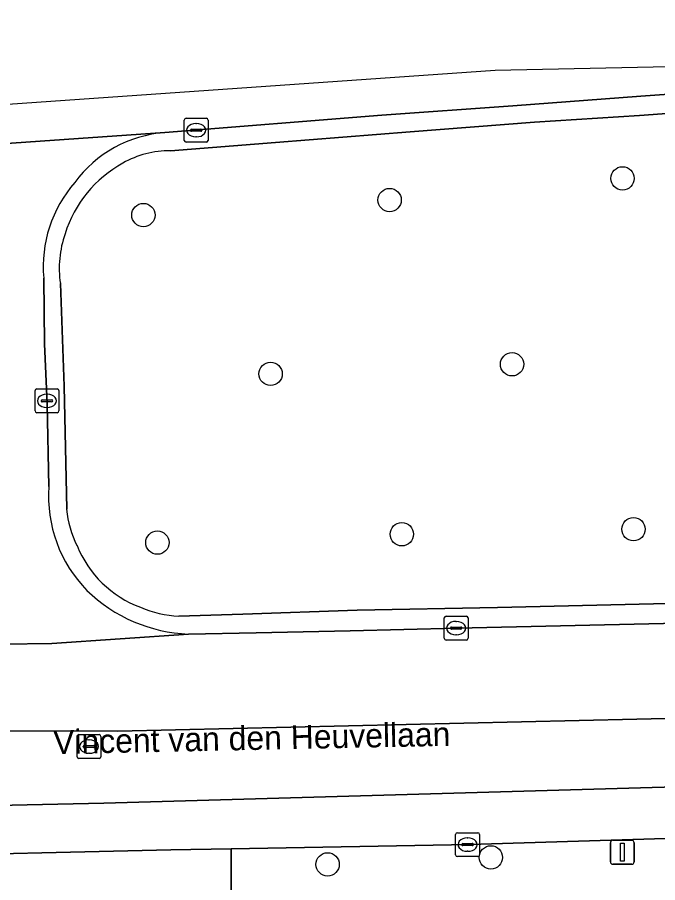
# Model space of a CAD drawing. Extents: x 160806 to 161707, y 383696 to 384148.
# Drawn here: x 161330.97 to 161357.82, y 384111.54 to 384147.79 of the extents above; entities that cross this region are included whole.
import ezdxf

# ---------------------------------------------------------------- set-up
doc = ezdxf.new("R2010")
doc.units = 0
for name, color, linetype in [('IMGEO_Berm_groen', 7, 'Continuous'), ('IMGEO_Boom', 7, 'Continuous'), ('IMGEO_Kolk', 7, 'Continuous'), ('IMGEO_Lichtmast', 7, 'Continuous'), ('IMGEO_Openbare_ruimte_label', 7, 'Continuous'), ('IMGEO_Rijbaan_lokaal_gesloten', 7, 'Continuous'), ('IMGEO_Rioolput', 7, 'Continuous'), ('IMGEO_Verkeerseiland_open', 7, 'Continuous'), ('IMGEO_Voetpad_open', 7, 'Continuous')]:
    doc.layers.add(name, color=color, linetype=linetype)

msp = doc.modelspace()

# ---------------------------------------------------------------- linework, layer by layer
at = {"layer": 'IMGEO_Berm_groen'}
for points in [[(161368.322, 384133.815), (161368.24, 384136.337), (161368.083, 384140.59), (161367.93, 384144.377), (161364.506, 384144.165), (161360.482, 384143.926), (161357.058, 384143.679), (161352.653, 384143.406), (161347.447, 384142.996), (161341.799, 384142.542), (161337.394, 384142.199)], [(161332.779, 384136.639), (161332.944, 384132.346), (161333.044, 384127.181)], [(161337.75, 384122.702), (161340.431, 384122.791), (161345.225, 384122.958), (161351.108, 384123.068), (161357.641, 384123.218), (161365.144, 384123.353), (161368.747, 384123.478), (161368.664, 384126.609), (161368.52, 384129.702), (161368.389, 384132.294), (161368.322, 384133.815)]]:
    msp.add_lwpolyline(points, dxfattribs=at)
for centre, radius, start, end in [((161337.351, 384138.259), 3.941, 89.3808, 119.716), ((161337.869, 384137.19), 5.126, 118.8204, 162.6198), ((161337.115, 384137.277), 4.383, 160.7646, 188.3704), ((161337.378, 384127.594), 4.354, 185.4426, 206.3586), ((161337.741, 384127.387), 4.6, 202.0341, 249.6037), ((161337.958, 384127.271), 4.574, 246.551, 267.3923)]:
    msp.add_arc(centre, radius, start, end, dxfattribs=at)
at = {"layer": 'IMGEO_Boom'}
for centre in [(161356.343, 384141.046), (161346.581, 384140.138), (161336.259, 384139.508), (161351.712, 384133.255), (161341.593, 384132.854), (161347.092, 384126.136), (161356.804, 384126.346), (161336.846, 384125.786), (161343.983, 384112.305), (161350.826, 384112.597)]:
    msp.add_circle(centre, 0.489, dxfattribs=at)
at = {"layer": 'IMGEO_Kolk'}
for p, q in [((161338.046, 384143.563), (161338.898, 384143.563)), ((161337.971, 384142.637), (161337.971, 384143.489)), ((161338.459, 384143.343), (161338.484, 384143.343)), ((161338.972, 384143.489), (161338.972, 384142.637)), ((161338.23, 384143.057), (161338.23, 384143.069)), ((161338.668, 384143.02), (161338.27, 384143.02)), ((161338.273, 384143.106), (161338.671, 384143.106)), ((161338.714, 384143.069), (161338.714, 384143.057)), ((161338.898, 384142.563), (161338.046, 384142.563)), ((161338.482, 384142.783), (161338.457, 384142.783)), ((161331.717, 384131.299), (161331.717, 384132.151)), ((161331.792, 384132.225), (161332.644, 384132.225)), ((161332.205, 384132.005), (161332.23, 384132.005)), ((161332.718, 384132.151), (161332.718, 384131.299)), ((161331.976, 384131.719), (161331.976, 384131.731)), ((161332.414, 384131.682), (161332.016, 384131.682)), ((161332.019, 384131.768), (161332.417, 384131.768)), ((161332.46, 384131.731), (161332.46, 384131.719)), ((161332.228, 384131.445), (161332.203, 384131.445)), ((161332.644, 384131.225), (161331.792, 384131.225)), ((161348.871, 384121.777), (161348.871, 384122.629)), ((161348.946, 384122.703), (161349.798, 384122.703)), ((161349.872, 384122.629), (161349.872, 384121.777)), ((161349.13, 384122.197), (161349.13, 384122.209)), ((161349.173, 384122.246), (161349.571, 384122.246)), ((161349.359, 384122.483), (161349.384, 384122.483)), ((161349.614, 384122.209), (161349.614, 384122.197)), ((161349.568, 384122.16), (161349.17, 384122.16)), ((161349.382, 384121.923), (161349.357, 384121.923)), ((161349.798, 384121.703), (161348.946, 384121.703)), ((161349.348, 384112.706), (161349.348, 384113.558)), ((161349.423, 384113.632), (161350.275, 384113.632)), ((161350.349, 384113.558), (161350.349, 384112.706)), ((161349.607, 384113.126), (161349.607, 384113.138)), ((161349.65, 384113.175), (161350.048, 384113.175)), ((161349.836, 384113.412), (161349.861, 384113.412)), ((161350.091, 384113.138), (161350.091, 384113.126)), ((161350.045, 384113.089), (161349.647, 384113.089)), ((161349.859, 384112.852), (161349.834, 384112.852)), ((161350.275, 384112.632), (161349.423, 384112.632))]:
    msp.add_line(p, q, dxfattribs=at)
for points in [[(161338.046, 384143.563), (161338.898, 384143.563)], [(161337.971, 384142.637), (161337.971, 384143.489)], [(161338.972, 384143.489), (161338.972, 384142.637)], [(161338.898, 384142.563), (161338.046, 384142.563)], [(161331.717, 384131.299), (161331.717, 384132.151)], [(161331.792, 384132.225), (161332.644, 384132.225)], [(161332.718, 384132.151), (161332.718, 384131.299)], [(161332.644, 384131.225), (161331.792, 384131.225)], [(161348.871, 384121.777), (161348.871, 384122.629)], [(161348.946, 384122.703), (161349.798, 384122.703)], [(161349.872, 384122.629), (161349.872, 384121.777)], [(161349.798, 384121.703), (161348.946, 384121.703)], [(161349.348, 384112.706), (161349.348, 384113.558)], [(161349.423, 384113.632), (161350.275, 384113.632)], [(161350.349, 384113.558), (161350.349, 384112.706)], [(161350.275, 384112.632), (161349.423, 384112.632)]]:
    msp.add_lwpolyline(points, dxfattribs=at)
for centre, radius, start, end in [((161338.048, 384143.487), 0.0765, 91.552, 178.448), ((161338.048, 384143.487), 0.0765, 91.552, 178.448), ((161338.896, 384143.487), 0.0765, 1.552, 88.448), ((161338.896, 384143.487), 0.0765, 1.552, 88.448), ((161338.27, 384143.066), 0.0403, 85.8775, 175.7526), ((161338.267, 384143.056), 0.0366, 178.938, 274.7102), ((161338.671, 384143.063), 0.043, 264.8664, 352.4533), ((161338.675, 384143.068), 0.0386, 1.7309, 96.639), ((161338.048, 384142.639), 0.0765, 181.552, 268.448), ((161338.048, 384142.639), 0.0765, 181.552, 268.448), ((161338.896, 384142.639), 0.0765, 271.552, 358.448), ((161338.896, 384142.639), 0.0765, 271.552, 358.448), ((161331.794, 384132.149), 0.0765, 91.552, 178.448), ((161331.794, 384132.149), 0.0765, 91.552, 178.448), ((161332.642, 384132.149), 0.0765, 1.552, 88.448), ((161332.642, 384132.149), 0.0765, 1.552, 88.448), ((161332.016, 384131.728), 0.0403, 85.8775, 175.7526), ((161332.013, 384131.718), 0.0366, 178.938, 274.7102), ((161332.417, 384131.725), 0.043, 264.8664, 352.4533), ((161332.421, 384131.73), 0.0386, 1.7309, 96.639), ((161331.794, 384131.301), 0.0765, 181.552, 268.448), ((161331.794, 384131.301), 0.0765, 181.552, 268.448), ((161332.642, 384131.301), 0.0765, 271.552, 358.448), ((161332.642, 384131.301), 0.0765, 271.552, 358.448), ((161348.948, 384122.627), 0.0765, 91.552, 178.448), ((161348.948, 384122.627), 0.0765, 91.552, 178.448), ((161349.796, 384122.627), 0.0765, 1.552, 88.448), ((161349.796, 384122.627), 0.0765, 1.552, 88.448), ((161349.17, 384122.206), 0.0403, 85.8775, 175.7526), ((161349.167, 384122.196), 0.0366, 178.938, 274.7102), ((161349.571, 384122.203), 0.043, 264.8664, 352.4533), ((161349.575, 384122.208), 0.0386, 1.7309, 96.639), ((161348.948, 384121.779), 0.0765, 181.552, 268.448), ((161348.948, 384121.779), 0.0765, 181.552, 268.448), ((161349.796, 384121.779), 0.0765, 271.552, 358.448), ((161349.796, 384121.779), 0.0765, 271.552, 358.448), ((161349.425, 384113.556), 0.0765, 91.552, 178.448), ((161349.425, 384113.556), 0.0765, 91.552, 178.448), ((161350.273, 384113.556), 0.0765, 1.552, 88.448), ((161350.273, 384113.556), 0.0765, 1.552, 88.448), ((161349.647, 384113.135), 0.0403, 85.8775, 175.7526), ((161349.644, 384113.125), 0.0366, 178.938, 274.7102), ((161350.048, 384113.132), 0.043, 264.8664, 352.4533), ((161350.052, 384113.137), 0.0386, 1.7309, 96.639), ((161349.425, 384112.708), 0.0765, 181.552, 268.448), ((161349.425, 384112.708), 0.0765, 181.552, 268.448), ((161350.273, 384112.708), 0.0765, 271.552, 358.448), ((161350.273, 384112.708), 0.0765, 271.552, 358.448)]:
    msp.add_arc(centre, radius, start, end, dxfattribs=at)
for centre, major_axis, ratio, start_param, end_param in [((161338.458, 384143.063), (-0.387, 0.002), 0.722429, 4.712389, 7.853982), ((161338.483, 384143.063), (-0.39, 0.002), 0.717154, 1.570796, 4.712389), ((161332.204, 384131.725), (-0.387, 0.002), 0.722429, 4.712389, 7.853982), ((161332.229, 384131.725), (-0.39, 0.002), 0.717154, 1.570796, 4.712389), ((161349.358, 384122.203), (-0.387, 0.002), 0.722429, 4.712389, 7.853982), ((161349.383, 384122.203), (-0.39, 0.002), 0.717154, 1.570796, 4.712389), ((161349.835, 384113.132), (-0.387, 0.002), 0.722429, 4.712389, 7.853982), ((161349.86, 384113.132), (-0.39, 0.002), 0.717154, 1.570796, 4.712389)]:
    msp.add_ellipse(centre, major_axis=major_axis, ratio=ratio, start_param=start_param, end_param=end_param, dxfattribs=at)
at = {"layer": 'IMGEO_Lichtmast'}
for p, q in [((161355.838, 384112.412), (161355.838, 384113.212)), ((161355.838, 384113.212), (161355.838, 384112.412)), ((161355.938, 384113.312), (161356.728, 384113.312)), ((161356.728, 384113.312), (161355.938, 384113.312)), ((161356.828, 384113.212), (161356.828, 384112.412)), ((161356.828, 384112.412), (161356.828, 384113.212)), ((161356.728, 384112.312), (161355.938, 384112.312)), ((161355.938, 384112.312), (161356.728, 384112.312))]:
    msp.add_line(p, q, dxfattribs=at)
msp.add_lwpolyline([(161356.258, 384113.187), (161356.408, 384113.187), (161356.408, 384112.437), (161356.258, 384112.437), (161356.258, 384113.187)], dxfattribs=at)
for centre, start, end in [((161355.938, 384113.212), 90, 180), ((161355.938, 384113.212), 90, 180), ((161356.728, 384113.212), 0, 90), ((161356.728, 384113.212), 360, 90), ((161355.938, 384112.412), 180, 270), ((161355.938, 384112.412), 180, 270), ((161356.728, 384112.412), 270, 0), ((161356.728, 384112.412), 270, 0)]:
    msp.add_arc(centre, 0.1, start, end, dxfattribs=at)
at = {"layer": 'IMGEO_Rijbaan_lokaal_gesloten'}
for points in [[(161327.703, 384142.304), (161337.16, 384142.963), (161346.257, 384143.694), (161351.743, 384144.08), (161357.112, 384144.482), (161367.896, 384145.252), (161368.23, 384145.276), (161372.889, 384145.38), (161388.411, 384145.768), (161389.577, 384145.803), (161400.516, 384146.018), (161403.919, 384146.182), (161420.401, 384146.492), (161435.415, 384146.872), (161436.002, 384146.887), (161453.438, 384147.374), (161453.468, 384147.793), (161426.579, 384147.153), (161350.999, 384145.561), (161261.88, 384139.347)], [(161337.16, 384142.963), (161327.703, 384142.304), (161317.535, 384141.567)], [(161332.301, 384128.136), (161332.223, 384131.597), (161332.111, 384134.119), (161332.082, 384136.87)], [(161386.513, 384123.225), (161373.645, 384122.84), (161368.776, 384122.738), (161362.942, 384122.615), (161358.059, 384122.401), (161349.424, 384122.203), (161344.922, 384122.082), (161340.98, 384122.012), (161338.149, 384121.956), (161332.428, 384121.56), (161328.301, 384121.504)], [(161317.569, 384121.54), (161324.44, 384121.451), (161328.301, 384121.504), (161332.428, 384121.56), (161338.149, 384121.956)], [(161369.031, 384118.661), (161335.182, 384117.881), (161322.396, 384117.897), (161316.729, 384118.038), (161308.839, 384118.481), (161293.967, 384119.32), (161278.23, 384120.232), (161260.613, 384121.23), (161260.358, 384117.771), (161260.762, 384117.753), (161269.102, 384117.385), (161271.935, 384117.201), (161286.376, 384116.275), (161306.289, 384115.145), (161321.017, 384114.547), (161327.538, 384114.71), (161334.603, 384114.873), (161357.592, 384115.525), (161367.726, 384115.798)], [(161322.396, 384117.897), (161335.182, 384117.881), (161369.031, 384118.661), (161369.029, 384118.892), (161371.257, 384119.002), (161371.267, 384118.709), (161419.052, 384119.747)], [(161367.726, 384115.798), (161357.592, 384115.525), (161334.603, 384114.873), (161327.538, 384114.71), (161321.017, 384114.547), (161306.289, 384115.145), (161286.376, 384116.275)], [(161286.829, 384115.858), (161286.809, 384115.322), (161286.671, 384111.658), (161320.761, 384112.539), (161322.18, 384112.562), (161323.478, 384112.593), (161325.397, 384112.64), (161337.406, 384112.917), (161339.944, 384112.961), (161349.937, 384113.134), (161360.425, 384113.454), (161372.09, 384113.647), (161383.418, 384113.963), (161394.707, 384114.341), (161402.739, 384114.468), (161412.541, 384114.668), (161420.828, 384114.943), (161428.175, 384115.173), (161429.374, 384115.2), (161429.79, 384115.242), (161431.294, 384115.336), (161439.917, 384115.574), (161446.149, 384115.774)]]:
    msp.add_lwpolyline(points, dxfattribs=at)
for centre, radius, start, end in [((161337.542, 384137.818), 5.16, 94.2466, 143.7156), ((161337.391, 384137.356), 5.331, 138.745, 185.2292), ((161337.886, 384127.711), 5.601, 175.6469, 224.5599), ((161338.39, 384128.388), 6.437, 225.7072, 267.8533)]:
    msp.add_arc(centre, radius, start, end, dxfattribs=at)
at = {"layer": 'IMGEO_Rioolput'}
for p, q in [((161333.48, 384116.814), (161333.48, 384117.666)), ((161333.555, 384117.74), (161334.407, 384117.74)), ((161333.968, 384117.52), (161333.993, 384117.52)), ((161334.481, 384117.666), (161334.481, 384116.814)), ((161333.739, 384117.234), (161333.739, 384117.246)), ((161334.177, 384117.197), (161333.779, 384117.197)), ((161333.782, 384117.283), (161334.18, 384117.283)), ((161334.223, 384117.246), (161334.223, 384117.234)), ((161334.407, 384116.74), (161333.555, 384116.74)), ((161333.991, 384116.96), (161333.966, 384116.96))]:
    msp.add_line(p, q, dxfattribs=at)
for points in [[(161333.48, 384116.814), (161333.48, 384117.666)], [(161333.555, 384117.74), (161334.407, 384117.74)], [(161334.481, 384117.666), (161334.481, 384116.814)], [(161334.407, 384116.74), (161333.555, 384116.74)]]:
    msp.add_lwpolyline(points, dxfattribs=at)
for centre, radius, start, end in [((161333.557, 384117.664), 0.0765, 91.552, 178.448), ((161333.557, 384117.664), 0.0765, 91.552, 178.448), ((161334.405, 384117.664), 0.0765, 1.552, 88.448), ((161334.405, 384117.664), 0.0765, 1.552, 88.448), ((161333.779, 384117.243), 0.0403, 85.8775, 175.7526), ((161333.776, 384117.233), 0.0366, 178.938, 274.7102), ((161334.18, 384117.24), 0.043, 264.8664, 352.4533), ((161334.184, 384117.245), 0.0386, 1.7309, 96.639), ((161333.557, 384116.816), 0.0765, 181.552, 268.448), ((161333.557, 384116.816), 0.0765, 181.552, 268.448), ((161334.405, 384116.816), 0.0765, 271.552, 358.448), ((161334.405, 384116.816), 0.0765, 271.552, 358.448)]:
    msp.add_arc(centre, radius, start, end, dxfattribs=at)
for centre, major_axis, ratio, start_param, end_param in [((161333.967, 384117.24), (-0.387, 0.002), 0.722429, 4.712389, 7.853982), ((161333.992, 384117.24), (-0.39, 0.002), 0.717154, 1.570796, 4.712389)]:
    msp.add_ellipse(centre, major_axis=major_axis, ratio=ratio, start_param=start_param, end_param=end_param, dxfattribs=at)
at = {"layer": 'IMGEO_Verkeerseiland_open'}
for points in [[(161337.394, 384142.199), (161341.799, 384142.542), (161347.447, 384142.996), (161352.653, 384143.406), (161357.058, 384143.679), (161360.482, 384143.926), (161364.506, 384144.165), (161367.93, 384144.377), (161367.896, 384145.252), (161357.112, 384144.482), (161351.743, 384144.08), (161346.257, 384143.694), (161337.16, 384142.963)], [(161332.082, 384136.87), (161332.111, 384134.119), (161332.223, 384131.597), (161332.301, 384128.136)], [(161333.044, 384127.181), (161332.944, 384132.346), (161332.779, 384136.639)], [(161338.149, 384121.956), (161340.98, 384122.012), (161344.922, 384122.082), (161349.424, 384122.203), (161358.059, 384122.401), (161362.942, 384122.615), (161368.776, 384122.738), (161368.747, 384123.478), (161365.144, 384123.353), (161357.641, 384123.218), (161351.108, 384123.068), (161345.225, 384122.958), (161340.431, 384122.791), (161337.75, 384122.702)]]:
    msp.add_lwpolyline(points, dxfattribs=at)
for centre, radius, start, end in [((161337.542, 384137.818), 5.16, 94.2466, 143.7156), ((161337.351, 384138.259), 3.941, 89.3808, 119.716), ((161337.869, 384137.19), 5.126, 118.8204, 162.6198), ((161337.391, 384137.356), 5.331, 138.745, 185.2292), ((161337.115, 384137.277), 4.383, 160.7646, 188.3704), ((161337.886, 384127.711), 5.601, 175.6469, 224.5599), ((161337.378, 384127.594), 4.354, 185.4426, 206.3586), ((161337.741, 384127.387), 4.6, 202.0341, 249.6037), ((161338.39, 384128.388), 6.437, 225.7072, 267.8533), ((161337.958, 384127.271), 4.574, 246.551, 267.3923)]:
    msp.add_arc(centre, radius, start, end, dxfattribs=at)
at = {"layer": 'IMGEO_Voetpad_open'}
for points in [[(161431.756, 384115.148), (161429.79, 384115.242), (161429.374, 384115.2), (161429.407, 384113.75), (161428.207, 384113.723), (161428.175, 384115.173), (161420.828, 384114.943), (161412.541, 384114.668), (161402.739, 384114.468), (161394.707, 384114.341), (161383.418, 384113.963), (161372.09, 384113.647), (161360.425, 384113.454), (161349.937, 384113.134), (161339.944, 384112.961), (161339.937, 384108.977), (161353.71, 384109.286), (161378.269, 384110.102), (161432.066, 384111.288)], [(161339.944, 384112.961), (161337.406, 384112.917), (161325.397, 384112.64), (161323.478, 384112.593), (161323.571, 384108.291), (161339.937, 384108.782), (161339.937, 384108.977)]]:
    msp.add_lwpolyline(points, close=True, dxfattribs=at)

# ---------------------------------------------------------------- texts
at = {"layer": 'IMGEO_Openbare_ruimte_label'}
msp.add_text('Vincent van den Heuvellaan', height=1, rotation=1.203, dxfattribs=at).set_placement((161332.486, 384116.923))

doc.saveas('drawing.dxf')
